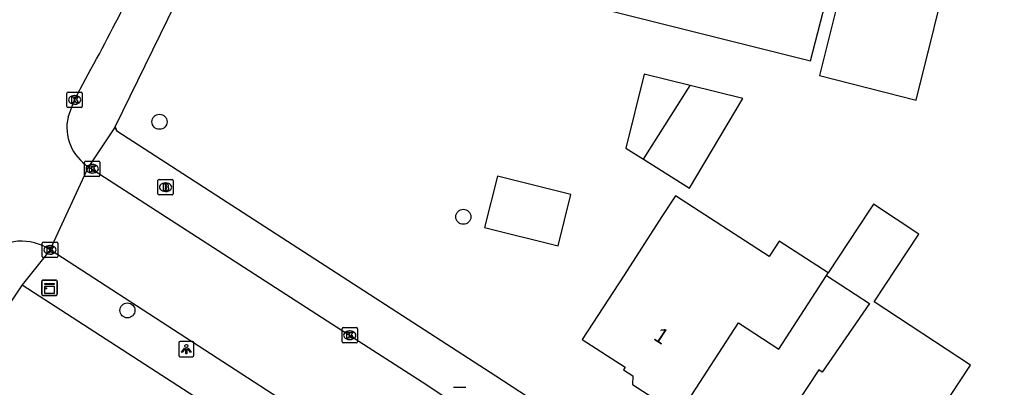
# Model space of a CAD drawing. Extents: x 161141 to 161601, y 381708 to 382245.
# Drawn here: x 161358.8 to 161422, y 382126.6 to 382150.6 of the extents above; entities that cross this region are included whole.
import ezdxf

# ---------------------------------------------------------------- set-up
doc = ezdxf.new("R2010")
doc.units = 0
for name, color, linetype in [('IMGEO_Boom', 7, 'Continuous'), ('IMGEO_Brandkraan', 7, 'Continuous'), ('IMGEO_Kast', 7, 'Continuous'), ('IMGEO_Kolk', 7, 'Continuous'), ('IMGEO_Lichtpunt', 7, 'Continuous'), ('IMGEO_Muur', 7, 'Continuous'), ('IMGEO_Pand', 7, 'Continuous'), ('IMGEO_Pand_nummerreeks', 7, 'Continuous'), ('IMGEO_Rijbaan_lokaal_open', 7, 'Continuous'), ('IMGEO_Voetpad_open', 7, 'Continuous')]:
    doc.layers.add(name, color=color, linetype=linetype)

msp = doc.modelspace()

# ---------------------------------------------------------------- linework, layer by layer
at = {"layer": 'IMGEO_Boom'}
for centre in [(161367.96, 382143.899), (161387.736, 382137.706), (161365.872, 382131.61)]:
    msp.add_circle(centre, 0.489, dxfattribs=at)
at = {"layer": 'IMGEO_Brandkraan'}
for p, q in [((161367.853, 382139.212), (161367.853, 382140.064)), ((161367.928, 382140.138), (161368.78, 382140.138)), ((161368.341, 382139.918), (161368.366, 382139.918)), ((161368.854, 382140.064), (161368.854, 382139.212)), ((161368.364, 382139.358), (161368.339, 382139.358)), ((161368.78, 382139.138), (161367.928, 382139.138))]:
    msp.add_line(p, q, dxfattribs=at)
for points in [[(161367.853, 382139.212), (161367.853, 382140.064)], [(161367.928, 382140.138), (161368.78, 382140.138)], [(161368.201, 382139.838), (161368.201, 382139.438), (161368.414, 382139.438)], [(161368.432, 382139.838), (161368.201, 382139.838)], [(161368.854, 382140.064), (161368.854, 382139.212)], [(161368.38, 382139.757), (161368.326, 382139.757), (161368.326, 382139.681)], [(161368.326, 382139.681), (161368.379, 382139.681)], [(161368.388, 382139.605), (161368.326, 382139.605), (161368.326, 382139.524)], [(161368.326, 382139.524), (161368.388, 382139.524)], [(161368.78, 382139.138), (161367.928, 382139.138)]]:
    msp.add_lwpolyline(points, dxfattribs=at)
for centre, radius, start, end in [((161367.93, 382140.062), 0.0765, 91.55205, 178.44795), ((161367.93, 382140.062), 0.0765, 91.55205, 178.44795), ((161368.436, 382139.693), 0.145, 59.4692, 91.53667), ((161368.778, 382140.062), 0.0765, 1.55205, 88.44795), ((161368.778, 382140.062), 0.0765, 1.55205, 88.44795), ((161367.93, 382139.214), 0.0765, 181.55205, 268.44795), ((161367.93, 382139.214), 0.0765, 181.55205, 268.44795), ((161368.381, 382139.719), 0.0379, 267.82845, 90.93552), ((161368.389, 382139.564), 0.0404, 269.87594, 90.50774), ((161368.42, 382139.689), 0.251, 268.66757, 293.53466), ((161368.461, 382139.74), 0.0922, 285.51372, 58.15012), ((161368.466, 382139.548), 0.105, 301.31148, 78.98903), ((161368.778, 382139.214), 0.0765, 271.55205, 358.44795), ((161368.778, 382139.214), 0.0765, 271.55205, 358.44795)]:
    msp.add_arc(centre, radius, start, end, dxfattribs=at)
for centre, major_axis, ratio, start_param, end_param in [((161368.34, 382139.638), (-0.387, 0.002), 0.722429, 4.712389, 7.853982), ((161368.365, 382139.638), (-0.39, 0.002), 0.717154, 1.570796, 4.712389)]:
    msp.add_ellipse(centre, major_axis=major_axis, ratio=ratio, start_param=start_param, end_param=end_param, dxfattribs=at)
at = {"layer": 'IMGEO_Kast'}
for p, q in [((161360.373, 382133.581), (161361.214, 382133.581)), ((161361.214, 382133.581), (161360.373, 382133.581)), ((161360.298, 382132.656), (161360.298, 382133.497)), ((161360.298, 382133.497), (161360.298, 382132.656)), ((161361.298, 382133.506), (161361.298, 382132.665)), ((161361.298, 382132.665), (161361.298, 382133.506)), ((161361.223, 382132.581), (161360.382, 382132.581)), ((161360.382, 382132.581), (161361.223, 382132.581))]:
    msp.add_line(p, q, dxfattribs=at)
for points in [[(161360.493, 382133.371), (161361.093, 382133.371), (161361.093, 382133.286), (161360.493, 382133.286), (161360.493, 382133.371)], [(161360.493, 382133.196), (161361.093, 382133.196), (161361.093, 382132.707), (161360.493, 382132.707), (161360.493, 382133.196)]]:
    msp.add_lwpolyline(points, dxfattribs=at)
msp.add_circle((161360.577, 382133.045), 0.0377, dxfattribs=at)
for centre, start, end in [((161360.376, 382133.503), 92.4484, 184.28452), ((161360.376, 382133.503), 92.4484, 184.28452), ((161361.22, 382133.503), 2.4484, 94.28452), ((161361.22, 382133.503), 2.4484, 94.28452), ((161360.376, 382132.659), 182.4484, 274.28452), ((161360.376, 382132.659), 182.4484, 274.28452), ((161361.22, 382132.659), 272.4484, 4.28452), ((161361.22, 382132.659), 272.4484, 4.28452)]:
    msp.add_arc(centre, 0.0779, start, end, dxfattribs=at)
at = {"layer": 'IMGEO_Kolk'}
for p, q in [((161361.935, 382144.903), (161361.935, 382145.755)), ((161362.01, 382145.829), (161362.862, 382145.829)), ((161362.423, 382145.609), (161362.448, 382145.609)), ((161362.936, 382145.755), (161362.936, 382144.903)), ((161362.446, 382145.049), (161362.421, 382145.049)), ((161362.862, 382144.829), (161362.01, 382144.829)), ((161363.08, 382140.414), (161363.08, 382141.266)), ((161363.155, 382141.34), (161364.007, 382141.34)), ((161363.568, 382141.12), (161363.593, 382141.12)), ((161364.081, 382141.266), (161364.081, 382140.414)), ((161363.591, 382140.56), (161363.566, 382140.56)), ((161364.007, 382140.34), (161363.155, 382140.34)), ((161360.407, 382136.054), (161361.259, 382136.054)), ((161360.332, 382135.128), (161360.332, 382135.98)), ((161360.82, 382135.834), (161360.845, 382135.834)), ((161361.333, 382135.98), (161361.333, 382135.128)), ((161361.259, 382135.054), (161360.407, 382135.054)), ((161360.843, 382135.274), (161360.818, 382135.274)), ((161379.839, 382129.562), (161379.839, 382130.414)), ((161379.914, 382130.488), (161380.766, 382130.488)), ((161380.84, 382130.414), (161380.84, 382129.562)), ((161380.327, 382130.268), (161380.352, 382130.268)), ((161380.766, 382129.488), (161379.914, 382129.488)), ((161380.35, 382129.708), (161380.325, 382129.708))]:
    msp.add_line(p, q, dxfattribs=at)
for points in [[(161361.935, 382144.903), (161361.935, 382145.755)], [(161362.01, 382145.829), (161362.862, 382145.829)], [(161362.256, 382145.529), (161362.379, 382145.529), (161362.379, 382145.378), (161362.509, 382145.529), (161362.673, 382145.529), (161362.527, 382145.378), (161362.68, 382145.129), (161362.528, 382145.129), (161362.443, 382145.293), (161362.379, 382145.226), (161362.379, 382145.129), (161362.256, 382145.129), (161362.256, 382145.529)], [(161362.936, 382145.755), (161362.936, 382144.903)], [(161362.862, 382144.829), (161362.01, 382144.829)], [(161363.08, 382140.414), (161363.08, 382141.266)], [(161363.155, 382141.34), (161364.007, 382141.34)], [(161364.081, 382141.266), (161364.081, 382140.414)], [(161363.401, 382141.04), (161363.524, 382141.04), (161363.524, 382140.889), (161363.654, 382141.04), (161363.818, 382141.04), (161363.672, 382140.889), (161363.825, 382140.64), (161363.673, 382140.64), (161363.588, 382140.804), (161363.524, 382140.737), (161363.524, 382140.64), (161363.401, 382140.64), (161363.401, 382141.04)], [(161364.007, 382140.34), (161363.155, 382140.34)], [(161360.407, 382136.054), (161361.259, 382136.054)], [(161360.332, 382135.128), (161360.332, 382135.98)], [(161360.653, 382135.754), (161360.776, 382135.754), (161360.776, 382135.603), (161360.906, 382135.754), (161361.07, 382135.754), (161360.924, 382135.603), (161361.077, 382135.354), (161360.925, 382135.354), (161360.84, 382135.518), (161360.776, 382135.451), (161360.776, 382135.354), (161360.653, 382135.354), (161360.653, 382135.754)], [(161361.333, 382135.98), (161361.333, 382135.128)], [(161361.259, 382135.054), (161360.407, 382135.054)], [(161379.839, 382129.562), (161379.839, 382130.414)], [(161379.914, 382130.488), (161380.766, 382130.488)], [(161380.84, 382130.414), (161380.84, 382129.562)], [(161380.16, 382130.188), (161380.283, 382130.188), (161380.283, 382130.037), (161380.413, 382130.188), (161380.577, 382130.188), (161380.431, 382130.037), (161380.584, 382129.788), (161380.432, 382129.788), (161380.347, 382129.952), (161380.283, 382129.885), (161380.283, 382129.788), (161380.16, 382129.788), (161380.16, 382130.188)], [(161380.766, 382129.488), (161379.914, 382129.488)]]:
    msp.add_lwpolyline(points, dxfattribs=at)
for centre, start, end in [((161362.012, 382145.753), 91.55205, 178.44795), ((161362.012, 382145.753), 91.55205, 178.44795), ((161362.86, 382145.753), 1.55205, 88.44795), ((161362.86, 382145.753), 1.55205, 88.44795), ((161362.012, 382144.905), 181.55205, 268.44795), ((161362.012, 382144.905), 181.55205, 268.44795), ((161362.86, 382144.905), 271.55205, 358.44795), ((161362.86, 382144.905), 271.55205, 358.44795), ((161363.157, 382141.264), 91.55205, 178.44795), ((161363.157, 382141.264), 91.55205, 178.44795), ((161364.005, 382141.264), 1.55205, 88.44795), ((161364.005, 382141.264), 1.55205, 88.44795), ((161363.157, 382140.416), 181.55205, 268.44795), ((161363.157, 382140.416), 181.55205, 268.44795), ((161364.005, 382140.416), 271.55205, 358.44795), ((161364.005, 382140.416), 271.55205, 358.44795), ((161360.409, 382135.978), 91.55205, 178.44795), ((161360.409, 382135.978), 91.55205, 178.44795), ((161361.257, 382135.978), 1.55205, 88.44795), ((161361.257, 382135.978), 1.55205, 88.44795), ((161360.409, 382135.13), 181.55205, 268.44795), ((161360.409, 382135.13), 181.55205, 268.44795), ((161361.257, 382135.13), 271.55205, 358.44795), ((161361.257, 382135.13), 271.55205, 358.44795), ((161379.916, 382130.412), 91.55205, 178.44795), ((161379.916, 382130.412), 91.55205, 178.44795), ((161380.764, 382130.412), 1.55205, 88.44795), ((161380.764, 382130.412), 1.55205, 88.44795), ((161379.916, 382129.564), 181.55205, 268.44795), ((161379.916, 382129.564), 181.55205, 268.44795), ((161380.764, 382129.564), 271.55205, 358.44795), ((161380.764, 382129.564), 271.55205, 358.44795)]:
    msp.add_arc(centre, 0.0765, start, end, dxfattribs=at)
for centre, major_axis, ratio, start_param, end_param in [((161362.422, 382145.329), (-0.387, 0.002), 0.722429, 4.712389, 7.853982), ((161362.447, 382145.329), (-0.39, 0.002), 0.717154, 1.570796, 4.712389), ((161363.567, 382140.84), (-0.387, 0.002), 0.722429, 4.712389, 7.853982), ((161363.592, 382140.84), (-0.39, 0.002), 0.717154, 1.570796, 4.712389), ((161360.819, 382135.554), (-0.387, 0.002), 0.722429, 4.712389, 7.853982), ((161360.844, 382135.554), (-0.39, 0.002), 0.717154, 1.570796, 4.712389), ((161380.326, 382129.988), (-0.387, 0.002), 0.722429, 4.712389, 7.853982), ((161380.351, 382129.988), (-0.39, 0.002), 0.717154, 1.570796, 4.712389)]:
    msp.add_ellipse(centre, major_axis=major_axis, ratio=ratio, start_param=start_param, end_param=end_param, dxfattribs=at)
at = {"layer": 'IMGEO_Lichtpunt'}
for p, q in [((161369.208, 382129.492), (161369.208, 382128.685)), ((161369.208, 382129.492), (161369.208, 382128.685)), ((161370.11, 382129.587), (161369.302, 382129.587)), ((161370.11, 382129.587), (161369.302, 382129.587)), ((161370.204, 382128.685), (161370.204, 382129.492)), ((161370.204, 382128.685), (161370.204, 382129.492)), ((161369.302, 382128.591), (161370.11, 382128.591)), ((161369.302, 382128.591), (161370.11, 382128.591)), ((161387.901, 382126.575), (161387.093, 382126.575)), ((161387.901, 382126.575), (161387.093, 382126.575))]:
    msp.add_line(p, q, dxfattribs=at)
for points in [[(161369.582, 382129.156), (161369.621, 382129.128), (161369.433, 382128.866), (161369.395, 382128.893), (161369.582, 382129.156)], [(161369.684, 382129.108), (161369.731, 382129.108), (161369.731, 382128.786), (161369.684, 382128.786), (161369.684, 382129.108)], [(161369.794, 382129.128), (161369.832, 382129.155), (161370.019, 382128.893), (161369.98, 382128.865), (161369.794, 382129.128)]]:
    msp.add_lwpolyline(points, dxfattribs=at)
msp.add_circle((161369.707, 382129.29), 0.0994, dxfattribs=at)
for centre, start, end in [((161369.302, 382129.492), 90, 180), ((161369.302, 382129.492), 90, 180), ((161370.11, 382129.492), 0, 90), ((161370.11, 382129.492), 0, 90), ((161369.302, 382128.685), 180, 270), ((161369.302, 382128.685), 180, 270), ((161370.11, 382128.685), 270, 0), ((161370.11, 382128.685), 270, 360)]:
    msp.add_arc(centre, 0.0946, start, end, dxfattribs=at)
at = {"layer": 'IMGEO_Muur'}
for points in [[(161365.084, 382143.565), (161369.98, 382153.637), (161372.26, 382158.835), (161374.321, 382163.969), (161377.586, 382172.934), (161380.259, 382181.034), (161381.949, 382183.375), (161384.186, 382184.996), (161387.058, 382185.651), (161389.844, 382185.251), (161418.52, 382178.097)], [(161365.084, 382143.565), (161365.175, 382143.293)], [(161389.855, 382127.317), (161365.175, 382143.293)]]:
    msp.add_lwpolyline(points, dxfattribs=at)
at = {"layer": 'IMGEO_Pand'}
for points in [[(161405.328, 382156.469), (161392.128, 382159.743), (161392.312, 382160.48), (161392.661, 382160.393), (161393.766, 382164.828), (161395.629, 382164.363), (161397.305, 382171.088), (161395.44, 382171.566), (161396.492, 382175.746), (161384.415, 382178.79), (161380.562, 382163.42), (161389.977, 382161.049), (161389.869, 382160.579), (161389.809, 382160.312), (161389.667, 382160.348), (161387.933, 382153.493), (161410.333, 382147.872), (161415.348, 382167.296), (161408.489, 382169.001), (161405.861, 382158.583), (161406.93, 382158.318), (161406.405, 382156.202), (161405.328, 382156.469)], [(161428.705, 382161.861), (161429.913, 382166.712), (161428.484, 382167.068), (161428.734, 382168.071), (161426.329, 382168.67), (161426.089, 382167.707), (161422.647, 382168.564), (161421.693, 382164.734), (161420.44, 382165.046), (161418.18, 382155.968), (161413.467, 382157.169), (161412.259, 382152.318), (161410.912, 382146.912), (161417.202, 382145.309), (161419.537, 382154.683), (161426.476, 382152.914), (161428.705, 382161.861)], [(161402.499, 382146.263), (161399.499, 382147.005), (161398.313, 382142.189), (161399.471, 382141.463)], [(161399.471, 382141.463), (161402.499, 382146.263)], [(161399.471, 382141.463), (161402.457, 382139.579), (161405.921, 382145.415), (161402.499, 382146.263)], [(161394.741, 382139.169), (161389.954, 382140.366), (161389.113, 382137.003), (161393.901, 382135.81), (161394.741, 382139.169)], [(161411.481, 382134.059), (161408.295, 382136.12), (161407.65, 382135.123), (161401.554, 382139.067), (161400.661, 382137.729), (161398.193, 382133.914), (161395.476, 382129.716), (161398.267, 382127.909), (161398.155, 382127.736), (161398.771, 382127.338), (161398.742, 382126.773), (161400.996, 382125.315), (161401.533, 382125.759), (161402.135, 382125.37), (161404.852, 382129.568), (161405.639, 382130.788), (161408.274, 382129.089), (161411.371, 382133.888)], [(161418.188, 382124.158), (161420.742, 382128.036), (161414.478, 382132.158), (161417.389, 382136.583), (161414.424, 382138.532), (161414.118, 382138.066), (161411.481, 382134.059)], [(161411.371, 382133.888), (161414.164, 382132.048), (161411.096, 382127.59), (161410.877, 382127.733), (161408.688, 382124.408)], [(161411.371, 382133.888), (161411.481, 382134.059)]]:
    msp.add_lwpolyline(points, dxfattribs=at)
at = {"layer": 'IMGEO_Rijbaan_lokaal_open'}
for points in [[(161362.007, 382144.211), (161362.436, 382145.329), (161363.133, 382146.669)], [(161360.833, 382135.554), (161363.341, 382140.967)], [(161363.341, 382140.967), (161378.876, 382130.938), (161381.534, 382129.214), (161385.362, 382126.757), (161388.136, 382124.895)], [(161499.796, 382045.589), (161498.051, 382046.741), (161477.592, 382059.945), (161473.195, 382062.836), (161460.477, 382071.037), (161453.542, 382075.54), (161442.527, 382082.644), (161435.549, 382087.163), (161421.669, 382096.147), (161415.306, 382100.289), (161401.761, 382109.008), (161398.574, 382111.058), (161389.569, 382116.981), (161386.277, 382119.018), (161382.915, 382121.211), (161379.746, 382123.279), (161360.833, 382135.554)]]:
    msp.add_lwpolyline(points, dxfattribs=at)
for centre, radius, start, end in [((161239.19, 382215.477), 141.762, 330.96283, 335.87332), ((161364.966, 382143.531), 3.036, 167.06335, 237.64361), ((161358.998, 382132.863), 3.257, 55.70433, 133.4178)]:
    msp.add_arc(centre, radius, start, end, dxfattribs=at)
at = {"layer": 'IMGEO_Voetpad_open'}
for points in [[(161365.084, 382143.565), (161369.98, 382153.637), (161372.26, 382158.835), (161374.321, 382163.969), (161377.586, 382172.934), (161380.259, 382181.034), (161381.949, 382183.375), (161384.186, 382184.996), (161387.058, 382185.651)], [(161365.084, 382143.565), (161363.341, 382140.967)], [(161523.437, 382040.853), (161500, 382056.07), (161450.498, 382088.211), (161408.789, 382114.947), (161389.855, 382127.317), (161365.175, 382143.293), (161365.084, 382143.565)], [(161360.833, 382135.554), (161359.011, 382133.266)], [(161359.011, 382133.266), (161357.507, 382131.037)], [(161359.011, 382133.266), (161498.24, 382043.117)]]:
    msp.add_lwpolyline(points, dxfattribs=at)

# ---------------------------------------------------------------- texts
at = {"layer": 'IMGEO_Pand_nummerreeks'}
msp.add_text('1', height=1, rotation=326.8695, dxfattribs=at).set_placement((161400.048, 382129.742))

doc.saveas('drawing.dxf')
